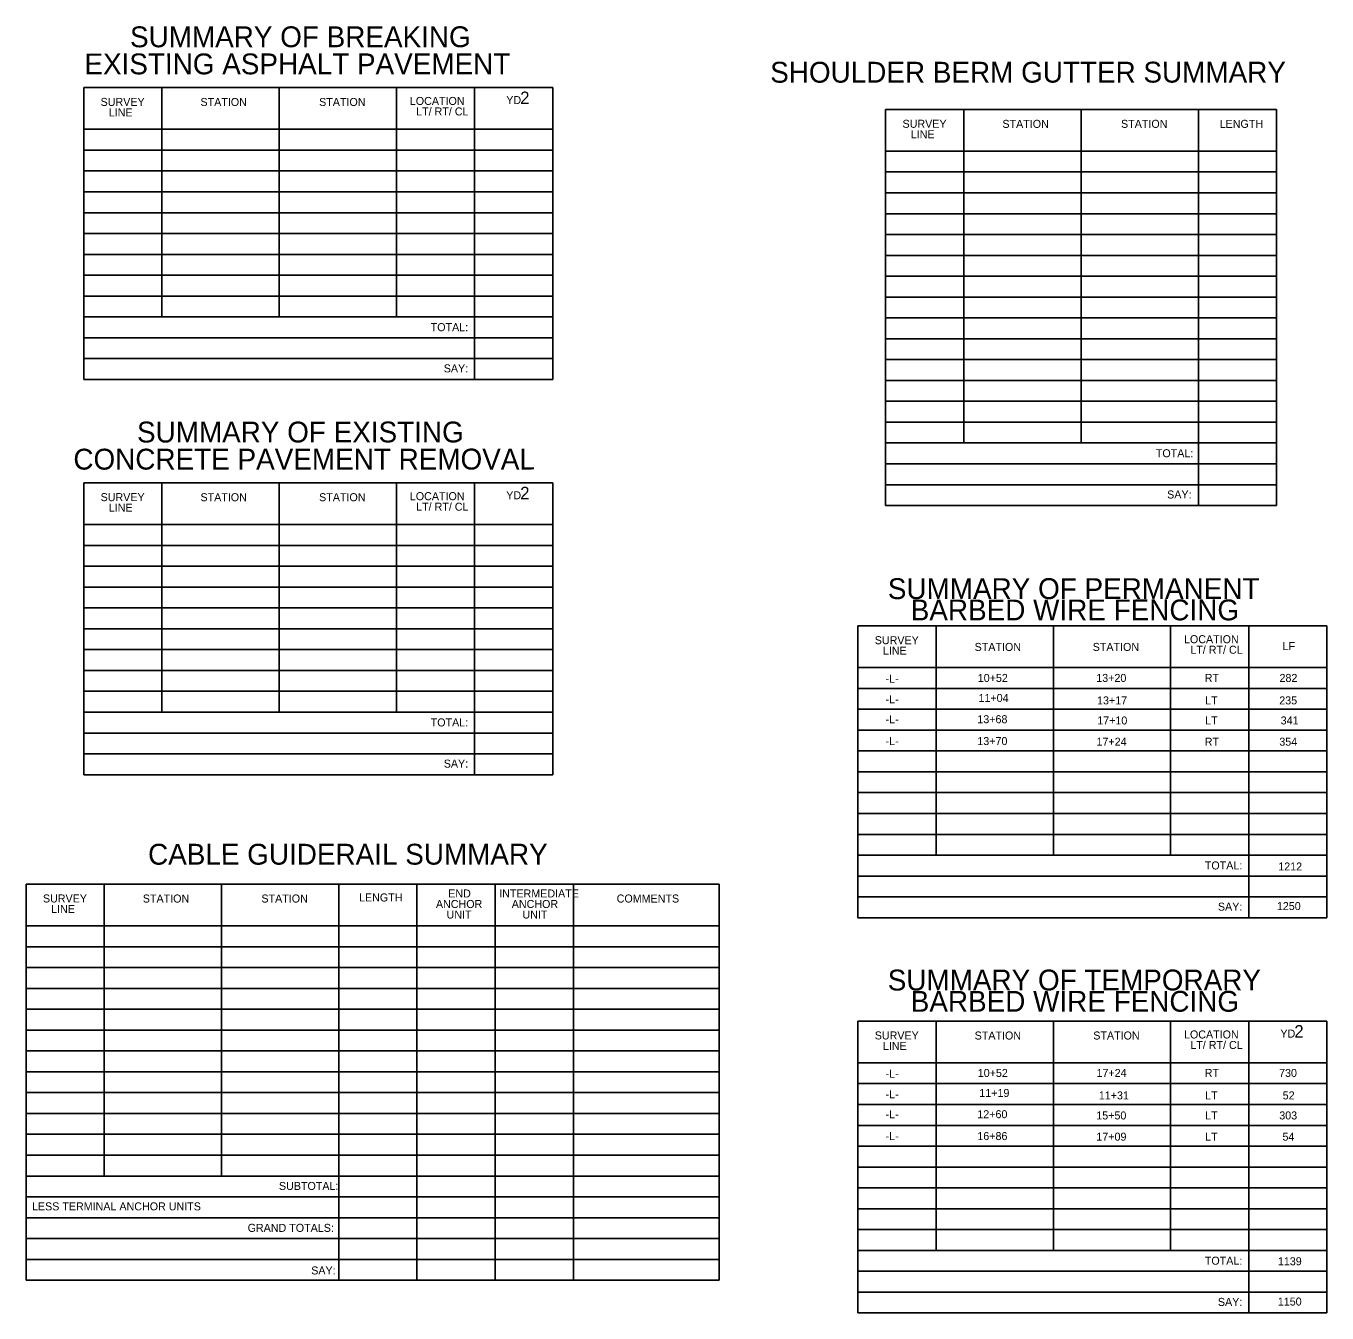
# Model space of a CAD drawing. Extents: x 1728265 to 1732106, y 539919 to 543766.
# Drawn here: x 1731325 to 1732106, y 540089 to 540861 of the extents above; entities that cross this region are included whole.
import ezdxf

# ---------------------------------------------------------------- set-up
doc = ezdxf.new("R2010")
doc.units = 0
for name, color, linetype in [('Default', 7, 'Continuous'), ('Sheet Summary Combination CELL', 7, 'Continuous'), ('Sheet Summary Combination Grid CELL', 7, 'Continuous')]:
    doc.layers.add(name, color=color, linetype=linetype)

msp = doc.modelspace()

# ---------------------------------------------------------------- linework, layer by layer
at = {"layer": 'Sheet Summary Combination CELL'}
for p, q in [((1731501.31, 540823.81), (1731501.31, 540823.81)), ((1731507.56, 540823.71), (1731507.56, 540823.71)), ((1731516.61, 540823.91), (1731516.61, 540823.91)), ((1731522.21, 540823.81), (1731522.21, 540823.81)), ((1731982.23, 540810.71), (1731982.23, 540810.71)), ((1731988.48, 540810.61), (1731988.48, 540810.61)), ((1731997.53, 540810.81), (1731997.53, 540810.81)), ((1732003.13, 540810.71), (1732003.13, 540810.71)), ((1731501.31, 540586.82), (1731501.31, 540586.82)), ((1731507.56, 540586.72), (1731507.56, 540586.72)), ((1731516.61, 540586.92), (1731516.61, 540586.92)), ((1731522.21, 540586.82), (1731522.21, 540586.82)), ((1731965.57, 540501.05), (1731965.57, 540501.05)), ((1731971.82, 540500.95), (1731971.82, 540500.95)), ((1731980.87, 540501.15), (1731980.87, 540501.15)), ((1731986.47, 540501.05), (1731986.47, 540501.05)), ((1731466.73, 540346.19), (1731466.73, 540346.19)), ((1731472.98, 540346.09), (1731472.98, 540346.09)), ((1731482.03, 540346.29), (1731482.03, 540346.29)), ((1731487.63, 540346.19), (1731487.63, 540346.19)), ((1731965.57, 540264.06), (1731965.57, 540264.06)), ((1731971.82, 540263.96), (1731971.82, 540263.96)), ((1731980.87, 540264.16), (1731980.87, 540264.16)), ((1731986.47, 540264.06), (1731986.47, 540264.06))]:
    msp.add_line(p, q, dxfattribs=at)
at = {"layer": 'Sheet Summary Combination Grid CELL'}
for p, q in [((1731360.06, 540823.86), (1731641.41, 540823.86)), ((1731360.06, 540823.86), (1731360.06, 540648.86)), ((1731406.96, 540823.86), (1731406.96, 540686.36)), ((1731477.31, 540823.86), (1731477.31, 540686.36)), ((1731547.61, 540823.86), (1731547.61, 540686.36)), ((1731594.51, 540823.86), (1731594.51, 540648.86)), ((1731641.41, 540823.86), (1731641.41, 540648.86)), ((1731840.98, 540810.76), (1732075.43, 540810.76)), ((1731840.98, 540810.76), (1731840.98, 540573.26)), ((1731887.88, 540810.76), (1731887.88, 540610.76)), ((1731958.23, 540810.76), (1731958.23, 540610.76)), ((1732028.53, 540810.76), (1732028.53, 540573.26)), ((1732075.43, 540810.76), (1732075.43, 540573.26)), ((1731360.06, 540798.86), (1731641.41, 540798.86)), ((1731360.06, 540786.36), (1731641.41, 540786.36)), ((1731840.98, 540785.76), (1732075.43, 540785.76)), ((1731360.06, 540773.86), (1731641.41, 540773.86)), ((1731840.98, 540773.26), (1732075.43, 540773.26)), ((1731360.06, 540761.36), (1731641.41, 540761.36)), ((1731840.98, 540760.76), (1732075.43, 540760.76)), ((1731360.06, 540748.86), (1731641.41, 540748.86)), ((1731840.98, 540748.26), (1732075.43, 540748.26)), ((1731360.06, 540736.36), (1731641.41, 540736.36)), ((1731840.98, 540735.76), (1732075.43, 540735.76)), ((1731360.06, 540723.86), (1731641.41, 540723.86)), ((1731840.98, 540723.26), (1732075.43, 540723.26)), ((1731360.06, 540711.36), (1731641.41, 540711.36)), ((1731840.98, 540710.76), (1732075.43, 540710.76)), ((1731360.06, 540698.86), (1731641.41, 540698.86)), ((1731840.98, 540698.26), (1732075.43, 540698.26)), ((1731360.06, 540686.36), (1731641.41, 540686.36)), ((1731840.98, 540685.76), (1732075.43, 540685.76)), ((1731360.06, 540673.86), (1731641.41, 540673.86)), ((1731840.98, 540673.26), (1732075.43, 540673.26)), ((1731360.06, 540661.36), (1731641.41, 540661.36)), ((1731840.98, 540660.76), (1732075.43, 540660.76)), ((1731360.06, 540648.86), (1731641.41, 540648.86)), ((1731840.98, 540648.26), (1732075.43, 540648.26)), ((1731840.98, 540635.76), (1732075.43, 540635.76)), ((1731840.98, 540635.76), (1732075.43, 540635.76)), ((1731840.98, 540623.26), (1732075.43, 540623.26)), ((1731840.98, 540610.76), (1732075.43, 540610.76)), ((1731840.98, 540598.26), (1732075.43, 540598.26)), ((1731360.06, 540586.87), (1731641.41, 540586.87)), ((1731360.06, 540586.87), (1731360.06, 540411.87)), ((1731406.96, 540586.87), (1731406.96, 540449.37)), ((1731477.31, 540586.87), (1731477.31, 540449.37)), ((1731547.61, 540586.87), (1731547.61, 540449.37)), ((1731594.51, 540586.87), (1731594.51, 540411.87)), ((1731641.41, 540586.87), (1731641.41, 540411.87)), ((1731840.98, 540585.76), (1732075.43, 540585.76)), ((1731840.98, 540573.26), (1732075.43, 540573.26)), ((1731360.06, 540561.87), (1731641.41, 540561.87)), ((1731360.06, 540549.37), (1731641.41, 540549.37)), ((1731360.06, 540536.87), (1731641.41, 540536.87)), ((1731360.06, 540524.37), (1731641.41, 540524.37)), ((1731360.06, 540511.87), (1731641.41, 540511.87)), ((1731360.06, 540499.37), (1731641.41, 540499.37)), ((1731824.32, 540501.1), (1732105.67, 540501.1)), ((1731824.32, 540501.1), (1731824.32, 540326.1)), ((1731871.22, 540501.1), (1731871.22, 540363.6)), ((1731941.57, 540501.1), (1731941.57, 540363.6)), ((1732011.87, 540501.1), (1732011.87, 540363.6)), ((1732058.77, 540501.1), (1732058.77, 540326.1)), ((1732105.67, 540501.1), (1732105.67, 540326.1)), ((1731360.06, 540486.87), (1731641.41, 540486.87)), ((1731360.06, 540474.37), (1731641.41, 540474.37)), ((1731824.32, 540476.1), (1732105.67, 540476.1)), ((1731360.06, 540461.87), (1731641.41, 540461.87)), ((1731824.32, 540463.6), (1732105.67, 540463.6)), ((1731360.06, 540449.37), (1731641.41, 540449.37)), ((1731824.32, 540451.1), (1732105.67, 540451.1)), ((1731360.06, 540436.87), (1731641.41, 540436.87)), ((1731824.32, 540438.6), (1732105.67, 540438.6)), ((1731824.32, 540426.1), (1732105.67, 540426.1)), ((1731360.06, 540424.37), (1731641.41, 540424.37)), ((1731360.06, 540411.87), (1731641.41, 540411.87)), ((1731824.32, 540413.6), (1732105.67, 540413.6)), ((1731824.32, 540401.1), (1732105.67, 540401.1)), ((1731824.32, 540388.6), (1732105.67, 540388.6)), ((1731824.32, 540376.1), (1732105.67, 540376.1)), ((1731824.32, 540363.6), (1732105.67, 540363.6)), ((1731824.32, 540351.1), (1732105.67, 540351.1)), ((1731325.48, 540346.24), (1731741.23, 540346.24)), ((1731325.48, 540346.24), (1731325.48, 540108.74)), ((1731372.38, 540346.24), (1731372.38, 540171.24)), ((1731442.73, 540346.24), (1731442.73, 540171.24)), ((1731513.03, 540346.24), (1731513.03, 540108.74)), ((1731559.93, 540346.24), (1731559.93, 540108.74)), ((1731606.83, 540346.24), (1731606.83, 540108.74)), ((1731653.73, 540346.24), (1731653.73, 540108.74)), ((1731741.23, 540346.24), (1731741.23, 540108.74)), ((1731824.32, 540338.6), (1732105.67, 540338.6)), ((1731824.32, 540326.1), (1732105.67, 540326.1)), ((1731325.48, 540321.24), (1731741.23, 540321.24)), ((1731325.48, 540308.74), (1731741.23, 540308.74)), ((1731325.48, 540296.24), (1731741.23, 540296.24)), ((1731325.48, 540283.74), (1731741.23, 540283.74)), ((1731325.48, 540271.24), (1731741.23, 540271.24)), ((1731824.32, 540264.11), (1732105.67, 540264.11)), ((1731824.32, 540264.11), (1731824.32, 540089.11)), ((1731871.22, 540264.11), (1731871.22, 540126.61)), ((1731941.57, 540264.11), (1731941.57, 540126.61)), ((1732011.87, 540264.11), (1732011.87, 540126.61)), ((1732058.77, 540264.11), (1732058.77, 540089.11)), ((1732105.67, 540264.11), (1732105.67, 540089.11)), ((1731325.48, 540258.74), (1731741.23, 540258.74)), ((1731325.48, 540246.24), (1731741.23, 540246.24)), ((1731824.32, 540239.11), (1732105.67, 540239.11)), ((1731325.48, 540233.74), (1731741.23, 540233.74)), ((1731824.32, 540226.61), (1732105.67, 540226.61)), ((1731325.48, 540221.24), (1731741.23, 540221.24)), ((1731325.48, 540208.74), (1731741.23, 540208.74)), ((1731824.32, 540214.11), (1732105.67, 540214.11)), ((1731824.32, 540201.61), (1732105.67, 540201.61)), ((1731325.48, 540196.24), (1731741.23, 540196.24)), ((1731824.32, 540189.11), (1732105.67, 540189.11)), ((1731325.48, 540183.74), (1731741.23, 540183.74)), ((1731824.32, 540176.61), (1732105.67, 540176.61)), ((1731325.48, 540171.24), (1731741.23, 540171.24)), ((1731824.32, 540164.11), (1732105.67, 540164.11)), ((1731325.48, 540158.74), (1731741.23, 540158.74)), ((1731325.48, 540146.24), (1731741.23, 540146.24)), ((1731824.32, 540151.61), (1732105.67, 540151.61)), ((1731824.32, 540139.11), (1732105.67, 540139.11)), ((1731325.48, 540133.74), (1731741.23, 540133.74)), ((1731824.32, 540126.61), (1732105.67, 540126.61)), ((1731325.48, 540121.24), (1731741.23, 540121.24)), ((1731824.32, 540114.11), (1732105.67, 540114.11)), ((1731325.48, 540108.74), (1731741.23, 540108.74)), ((1731824.32, 540101.61), (1732105.67, 540101.61)), ((1731824.32, 540089.11), (1732105.67, 540089.11))]:
    msp.add_line(p, q, dxfattribs=at)

# ---------------------------------------------------------------- texts
at = {"layer": 'Default'}
for s, p in [('-L-', (1731840.99, 540466.99)), ('10+52', (1731896.25, 540467.49)), ('13+20', (1731967.32, 540467.49)), ('RT', (1732032.34, 540467.49)), ('282', (1732077.21, 540467.49)), ('-L-', (1731840.99, 540454.75)), ('11+04', (1731896.7, 540455.47)), ('13+17', (1731967.78, 540454.02)), ('LT', (1732032.63, 540454.02)), ('235', (1732077.05, 540454.02)), ('-L-', (1731840.99, 540442.73)), ('13+68', (1731895.99, 540442.73)), ('17+10', (1731967.89, 540442)), ('LT', (1732032.63, 540442)), ('341', (1732077.9, 540442)), ('-L-', (1731840.99, 540429.63)), ('13+70', (1731895.99, 540429.63)), ('17+24', (1731967.45, 540429.26)), ('RT', (1732032.34, 540429.26)), ('354', (1732077.09, 540429.26)), ('1212', (1732076.47, 540354.43)), ('1250', (1732075.63, 540330.7)), ('-L-', (1731840.99, 540230.14)), ('10+52', (1731896.25, 540230.64)), ('17+24', (1731967.45, 540230.64)), ('RT', (1732032.34, 540230.64)), ('730', (1732076.95, 540230.64)), ('11+19', (1731897.18, 540218.63)), ('-L-', (1731840.99, 540217.9)), ('11+31', (1731968.84, 540217.17)), ('LT', (1732032.63, 540217.17)), ('52', (1732079.11, 540217.17)), ('-L-', (1731840.99, 540205.89)), ('12+60', (1731895.99, 540205.89)), ('15+50', (1731967.32, 540205.16)), ('LT', (1732032.63, 540205.16)), ('303', (1732077.06, 540205.16)), ('-L-', (1731840.99, 540192.78)), ('16+86', (1731896, 540192.78)), ('17+09', (1731967.36, 540192.42)), ('LT', (1732032.63, 540192.42)), ('54', (1732078.98, 540192.42)), ('1139', (1732076.24, 540117.71)), ('1150', (1732076.2, 540093.56))]:
    msp.add_text(s, height=4.8, dxfattribs=at).set_placement(p)
at = {"layer": 'Sheet Summary Combination CELL'}
for s, p in [('SUMMARY OF BREAKING', (1731387.83, 540848.05)), ('EXISTING ASPHALT PAVEMENT', (1731360.48, 540831.8)), ('SHOULDER BERM GUTTER SUMMARY', (1731771.77, 540826.81)), ('SUMMARY OF EXISTING', (1731392.02, 540611.06)), ('CONCRETE PAVEMENT REMOVAL', (1731353.88, 540594.81)), ('SUMMARY OF PERMANENT', (1731842.32, 540517.16)), ('BARBED WIRE FENCING', (1731856.06, 540504.39)), ('CABLE GUIDERAIL SUMMARY', (1731398.67, 540357.91)), ('SUMMARY OF TEMPORARY', (1731842.26, 540282.48)), ('BARBED WIRE FENCING', (1731856.06, 540269.71))]:
    msp.add_text(s, height=12.5001, rotation=0.01193, dxfattribs=at).set_placement(p)
for s, p in [('SURVEY', (1731370.21, 540812.88)), ('STATION', (1731430.11, 540812.82)), ('STATION', (1731501.25, 540812.84)), ('LOCATION', (1731555.66, 540813.46)), ('LINE', (1731375.11, 540806.58)), ('LT/ RT/ CL', (1731559.45, 540807.16)), ('SURVEY', (1731851.13, 540799.77)), ('STATION', (1731911.04, 540799.72)), ('STATION', (1731982.17, 540799.73)), ('LENGTH', (1732041.3, 540799.73)), ('LINE', (1731856.04, 540793.47)), ('TOTAL:', (1731568.16, 540677.81)), ('SAY:', (1731576, 540653.1)), ('TOTAL:', (1732003.04, 540602.21)), ('SAY:', (1732009.82, 540577.49)), ('SURVEY', (1731370.21, 540575.89)), ('LINE', (1731375.11, 540569.59)), ('STATION', (1731430.11, 540575.84)), ('STATION', (1731501.25, 540575.85)), ('LOCATION', (1731555.66, 540576.47)), ('LT/ RT/ CL', (1731559.45, 540570.17)), ('SURVEY', (1731834.47, 540490.11)), ('LINE', (1731839.37, 540483.81)), ('STATION', (1731894.37, 540486.08)), ('STATION', (1731965.17, 540486.08)), ('LOCATION', (1732019.92, 540490.7)), ('LT/ RT/ CL', (1732023.71, 540484.4)), ('TOTAL:', (1731568.16, 540440.82)), ('SAY:', (1731576, 540416.11)), ('TOTAL:', (1732032.42, 540355.05)), ('SURVEY', (1731335.62, 540335.26)), ('STATION', (1731395.53, 540335.21)), ('STATION', (1731466.66, 540335.22)), ('LENGTH', (1731525.2, 540335.84)), ('END', (1731578.66, 540338.24)), ('INTERMEDIATE', (1731609.25, 540338.24)), ('COMMENTS', (1731679.7, 540335.22)), ('LINE', (1731340.53, 540328.96)), ('ANCHOR', (1731571.3, 540331.94)), ('ANCHOR', (1731616.77, 540331.94)), ('SAY:', (1732040.26, 540330.34)), ('UNIT', (1731577.69, 540325.64)), ('UNIT', (1731623.16, 540325.64)), ('SURVEY', (1731834.47, 540253.13)), ('STATION', (1731894.37, 540253.07)), ('STATION', (1731965.51, 540253.09)), ('LOCATION', (1732019.92, 540253.71)), ('LINE', (1731839.37, 540246.83)), ('LT/ RT/ CL', (1732023.71, 540247.41)), ('SUBTOTAL:', (1731477.15, 540162.87)), ('LESS TERMINAL ANCHOR UNITS', (1731329.05, 540150.63)), ('GRAND TOTALS:', (1731458.37, 540137.75)), ('TOTAL:', (1732032.42, 540118.06)), ('SAY:', (1731496.51, 540112.21)), ('SAY:', (1732040.26, 540093.35))]:
    msp.add_text(s, height=4.8, dxfattribs=at).set_placement(p)
at = {"layer": 'Sheet Summary Combination Grid CELL'}
for s, height, p in [('YD', 4.8, (1731613.47, 540813.98)), ('2', 7.5, (1731621.84, 540813.98)), ('YD', 4.8, (1731613.47, 540577)), ('2', 7.5, (1731621.84, 540577)), ('LF', 4.8, (1732079.04, 540486.54)), ('YD', 4.8, (1732077.73, 540254.23)), ('2', 7.5, (1732086.1, 540254.23))]:
    msp.add_text(s, height=height, dxfattribs=at).set_placement(p)

doc.saveas('drawing.dxf')
